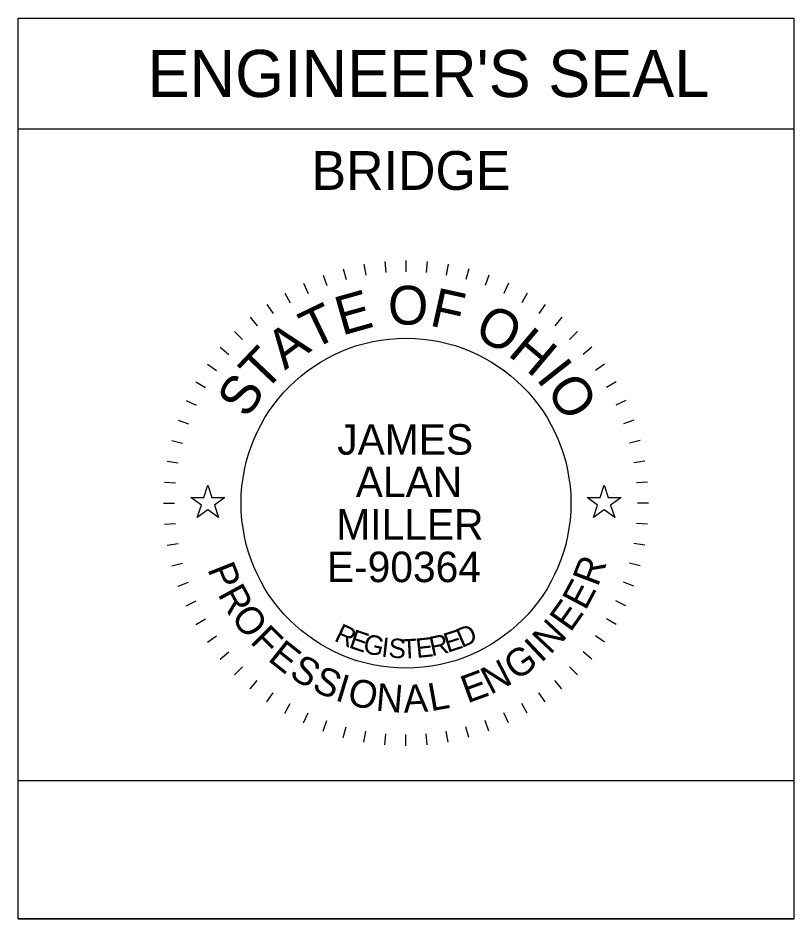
# Model space of a CAD drawing. Extents: x 0 to 39.4, y 0 to 22.
# Drawn here: x 36.614 to 39.414, y 0.5 to 3.75 of the extents above; entities that cross this region are included whole.
import ezdxf

# ---------------------------------------------------------------- set-up
doc = ezdxf.new("R2010")
doc.units = 0
doc.layers.add('Default', color=7, linetype='Continuous')
doc.layers.add('SH_Data', color=7, linetype='Continuous')

msp = doc.modelspace()

# ---------------------------------------------------------------- linework, layer by layer
at = {"layer": 'Default'}
for points in [[(37.2379, 2.02), (37.2848, 2.02), (37.2993, 2.0645), (37.3138, 2.02), (37.3607, 2.02), (37.3228, 1.9924), (37.3373, 1.9478), (37.2993, 1.9754), (37.2613, 1.9478), (37.2758, 1.9924)], [(38.6679, 2.02), (38.7148, 2.02), (38.7293, 2.0645), (38.7438, 2.02), (38.7907, 2.02), (38.7528, 1.9924), (38.7673, 1.9478), (38.7293, 1.9754), (38.6913, 1.9478), (38.7058, 1.9924)]]:
    msp.add_lwpolyline(points, close=True, dxfattribs=at)
at = {"layer": 'SH_Data'}
for p, q in [((36.6143, 0.5), (36.6143, 3.75)), ((36.6143, 3.75), (39.4143, 3.75)), ((39.4143, 3.75), (39.4143, 0.5)), ((36.6143, 3.35), (39.4143, 3.35)), ((37.8624, 2.8617), (37.8693, 2.8223)), ((37.938, 2.8717), (37.9415, 2.8318)), ((38.0143, 2.875), (38.0143, 2.835)), ((38.0906, 2.8717), (38.0871, 2.8318)), ((38.1663, 2.8617), (38.1593, 2.8223)), ((37.7878, 2.8452), (37.7982, 2.8065)), ((38.2408, 2.8452), (38.2304, 2.8065)), ((37.715, 2.8222), (37.7287, 2.7846)), ((38.3136, 2.8222), (38.2999, 2.7846)), ((37.6445, 2.793), (37.6614, 2.7568)), ((38.3841, 2.793), (38.3672, 2.7568)), ((37.5768, 2.7578), (37.5968, 2.7231)), ((38.4518, 2.7578), (38.4318, 2.7231)), ((37.5124, 2.7168), (37.5354, 2.684)), ((38.5162, 2.7168), (38.4932, 2.684)), ((37.4519, 2.6703), (37.4776, 2.6396)), ((38.5768, 2.6703), (38.551, 2.6396)), ((37.3956, 2.6187), (37.4239, 2.5904)), ((38.633, 2.6187), (38.6047, 2.5904)), ((37.344, 2.5624), (37.3747, 2.5367)), ((38.6846, 2.5624), (38.654, 2.5367)), ((37.2976, 2.5019), (37.3303, 2.4789)), ((38.7311, 2.5019), (38.6983, 2.4789)), ((37.2565, 2.4375), (37.2912, 2.4175)), ((38.7721, 2.4375), (38.7374, 2.4175)), ((37.2213, 2.3698), (37.2575, 2.3529)), ((38.8073, 2.3698), (38.7711, 2.3529)), ((37.1921, 2.2993), (37.2297, 2.2856)), ((38.8365, 2.2993), (38.799, 2.2856)), ((37.1691, 2.2265), (37.2078, 2.2161)), ((38.8595, 2.2265), (38.8209, 2.2161)), ((37.1526, 2.1519), (37.192, 2.145)), ((38.876, 2.1519), (38.8366, 2.145)), ((37.1426, 2.0763), (37.1825, 2.0728)), ((38.886, 2.0763), (38.8461, 2.0728)), ((37.1393, 2), (37.1793, 2)), ((38.8893, 2), (38.8493, 2)), ((37.1426, 1.9237), (37.1825, 1.9272)), ((38.886, 1.9237), (38.8461, 1.9272)), ((37.1526, 1.8481), (37.192, 1.855)), ((38.876, 1.8481), (38.8366, 1.855)), ((37.1691, 1.7735), (37.2078, 1.7839)), ((38.8595, 1.7735), (38.8209, 1.7839)), ((37.1921, 1.7007), (37.2297, 1.7144)), ((38.8365, 1.7007), (38.799, 1.7144)), ((37.2213, 1.6302), (37.2575, 1.6471)), ((38.8073, 1.6302), (38.7711, 1.6471)), ((37.2565, 1.5625), (37.2912, 1.5825)), ((38.7721, 1.5625), (38.7374, 1.5825)), ((37.2976, 1.4981), (37.3303, 1.5211)), ((38.7311, 1.4981), (38.6983, 1.5211)), ((37.344, 1.4376), (37.3747, 1.4633)), ((38.6846, 1.4376), (38.654, 1.4633)), ((37.3956, 1.3813), (37.4239, 1.4096)), ((38.633, 1.3813), (38.6047, 1.4096)), ((37.4519, 1.3297), (37.4776, 1.3604)), ((38.5768, 1.3297), (38.551, 1.3604)), ((37.5124, 1.2832), (37.5354, 1.316)), ((38.5162, 1.2832), (38.4932, 1.316)), ((37.5768, 1.2422), (37.5968, 1.2769)), ((38.4518, 1.2422), (38.4318, 1.2769)), ((37.6445, 1.207), (37.6614, 1.2432)), ((38.3841, 1.207), (38.3672, 1.2432)), ((37.715, 1.1778), (37.7287, 1.2154)), ((38.3136, 1.1778), (38.2999, 1.2154)), ((37.7878, 1.1548), (37.7982, 1.1935)), ((37.8624, 1.1383), (37.8693, 1.1777)), ((38.1663, 1.1383), (38.1593, 1.1777)), ((38.2408, 1.1548), (38.2304, 1.1935)), ((37.938, 1.1283), (37.9415, 1.1682)), ((38.0143, 1.125), (38.0143, 1.165)), ((38.0906, 1.1283), (38.0871, 1.1682)), ((36.6143, 0.5), (39.4143, 0.5))]:
    msp.add_line(p, q, dxfattribs=at)
msp.add_lwpolyline([(36.6143, 0.5), (36.6143, 1), (39.4143, 1), (39.4143, 0.5)], close=True, dxfattribs=at)
msp.add_circle((38.0143, 2), 0.595, dxfattribs=at)

# ---------------------------------------------------------------- texts
for s, height, p in [("ENGINEER'S SEAL", 0.17, (37.0819, 3.465)), ('BRIDGE', 0.14, (37.6733, 3.13)), ('JAMES ', 0.11, (37.7662, 2.1749)), ('ALAN', 0.11, (37.833, 2.0216)), ('MILLER', 0.11, (37.7627, 1.8684)), ('E-90364', 0.11, (37.7288, 1.7151))]:
    msp.add_text(s, height=height, dxfattribs=at).set_placement(p)
for s, height, rotation, p in [('E', 0.14, 15.7571, (37.7827, 2.6038)), ('O', 0.14, 359.7812, (37.949, 2.6443)), ('F', 0.14, 347.4362, (38.0954, 2.6417)), ('T', 0.14, 25.7167, (37.6759, 2.5518)), ('O', 0.14, 332.2586, (38.2541, 2.6015)), ('A', 0.14, 36.4747, (37.5777, 2.4781)), ('H', 0.14, 319.9136, (38.3775, 2.5361)), ('T', 0.14, 46.4344, (37.5026, 2.3964)), ('I', 0.14, 308.367, (38.4808, 2.4483)), ('S', 0.14, 57.1924, (37.4424, 2.3014)), ('O', 0.14, 303.1491, (38.5165, 2.4089)), ('P', 0.1, 291.494, (37.2966, 1.7621)), ('R', 0.1, 69.2322, (38.7063, 1.6954)), ('E', 0.1, 61.9951, (38.6619, 1.6098)), ('R', 0.1, 298.7311, (37.3333, 1.6717)), ('O', 0.1, 306.4666, (37.3798, 1.5883)), ('E', 0.1, 54.758, (38.6076, 1.5314)), ('F', 0.1, 314.7068, (37.4486, 1.4983)), ('R', 0.07, 334.487, (37.7518, 1.5051)), ('N', 0.1, 47.0224, (38.5345, 1.4508)), ('E', 0.07, 341.04, (37.8049, 1.4801)), ('E', 0.07, 17.6836, (38.1641, 1.4602)), ('D', 0.07, 23.3052, (38.2153, 1.477)), ('E', 0.1, 321.4393, (37.5121, 1.4348)), ('G', 0.07, 347.4752, (37.8558, 1.4618)), ('I', 0.07, 353.7858, (37.9234, 1.4468)), ('S', 0.07, 356.8926, (37.9501, 1.4429)), ('T', 0.07, 3.0061, (38, 1.4387)), ('E', 0.07, 6.0117, (38.0533, 1.4412)), ('R', 0.07, 11.9184, (38.1068, 1.4474)), ('I', 0.1, 43.287, (38.5012, 1.4214)), ('G', 0.1, 35.0469, (38.4124, 1.357)), ('S', 0.1, 328.6764, (37.5886, 1.3752)), ('N', 0.1, 27.3113, (38.3188, 1.3075)), ('S', 0.1, 335.9134, (37.6707, 1.3266)), ('E', 0.1, 20.0742, (38.2355, 1.277)), ('I', 0.1, 343.1505, (37.7549, 1.2897)), ('O', 0.1, 346.8859, (37.7982, 1.2751)), ('N', 0.1, 355.1261, (37.9031, 1.2517)), ('A', 0.1, 2.8617, (38.0066, 1.2437)), ('L', 0.1, 10.0987, (38.1037, 1.249))]:
    msp.add_text(s, height=height, rotation=rotation, dxfattribs=at).set_placement(p)

doc.saveas('drawing.dxf')
